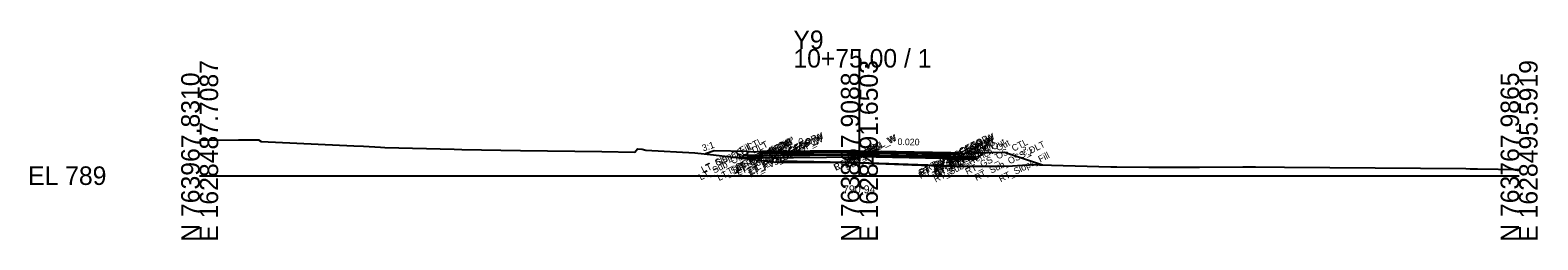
# Model space of a CAD drawing. Extents: x -26 to 203, y -10 to 6017.
# Drawn here: x -25.7 to 202.8, y 1490.3 to 1522 of the extents above; entities that cross this region are included whole.
import ezdxf

# ---------------------------------------------------------------- set-up
doc = ezdxf.new("R2010")
doc.units = 0
for name, color, linetype in [('Default', 7, 'Continuous'), ('Exist Cross Section Cell', 7, 'Continuous'), ('Exist XS Center Line Elevation Label', 7, 'Continuous'), ('Exist XS Ground Line', 7, 'Continuous'), ('Prop CMT Concrete Structures', 7, 'Continuous'), ('Prop CMT Pvmt Course 1', 7, 'Continuous'), ('Prop CMT Pvmt Course 1 Wedge', 7, 'Continuous'), ('Prop CMT Pvmt Course 2', 7, 'Continuous'), ('Prop CMT Pvmt Course 2 Wedge', 7, 'Continuous'), ('Prop CMT Pvmt Course 3', 7, 'Continuous'), ('Prop CMT Pvmt Course 3 Wedge', 7, 'Continuous'), ('Prop CMT Pvmt Surface', 7, 'Continuous'), ('Prop CMT Pvmt Surface Shoulder', 7, 'Continuous'), ('Prop CMT Pvmt Wedge Surface 2', 7, 'Continuous'), ('Prop CMT Pvmt Wedge Surface 3', 7, 'Continuous'), ('Prop CMT Shld Paved Course 1', 7, 'Continuous'), ('Prop CMT Shld Paved Course 2', 7, 'Continuous'), ('Prop CMT Shld Paved Course 3', 7, 'Continuous'), ('Prop CMT Slope Grass', 7, 'Continuous'), ('Prop CMT Subgrade Earthwork', 7, 'Continuous'), ('Prop XS SE Text', 7, 'Continuous'), ('Prop XS Side Slope Text', 7, 'Continuous'), ('Scratch_Level_0', 7, 'Continuous')]:
    doc.layers.add(name, color=color, linetype=linetype)

msp = doc.modelspace()

# ---------------------------------------------------------------- linework, layer by layer
at = {"layer": 'Exist Cross Section Cell'}
for p, q in [((100, 1500), (100, 1519.15)), ((0, 1500), (100, 1500)), ((100, 1500), (200, 1500))]:
    msp.add_line(p, q, dxfattribs=at)
at = {"layer": 'Exist XS Ground Line'}
msp.add_lwpolyline([(0, 1505.38), (5.87, 1505.43), (8.9, 1505.42), (9.31, 1505.16), (23.36, 1504.5), (24.83, 1504.44), (27.39, 1504.3), (28.08, 1504.26), (38.56, 1504.03), (39.75, 1503.98), (48.62, 1503.82), (60.96, 1503.65), (65.95, 1503.55), (66.37, 1504.05), (67.07, 1503.99), (67.63, 1503.87), (75.08, 1503.47), (77.9, 1503.15), (84.7, 1502.36), (86.09, 1502.21), (87.51, 1502.03), (94.47, 1502.03), (98.1, 1502.01), (100, 1501.94), (107.93, 1501.64), (113.86, 1501.45), (120.43, 1501.43), (120.98, 1501.45), (123.23, 1501.51), (124.73, 1501.61), (126.7, 1501.67), (127.29, 1501.65), (138.13, 1501.33), (139.04, 1501.36), (143.85, 1501.31), (148.08, 1501.31), (151.55, 1501.29), (158.1, 1501.35), (160.05, 1501.34), (164.43, 1501.31), (191.91, 1501.07), (192.59, 1501.05), (192.97, 1501.05), (193.67, 1501.04), (200, 1500.93)], dxfattribs=at)
at = {"layer": 'Prop CMT Concrete Structures'}
for points in [[(83, 1503.64), (83, 1503.06), (85, 1503.06)], [(85, 1503.64), (84, 1503.56), (83, 1503.64)], [(85, 1503.06), (85, 1503.64)], [(117, 1503.45), (117, 1502.87), (115, 1502.87)], [(115, 1503.45), (116, 1503.37), (117, 1503.45)], [(115, 1502.87), (115, 1503.45)]]:
    msp.add_lwpolyline(points, dxfattribs=at)
at = {"layer": 'Prop CMT Pvmt Course 1'}
for points in [[(100, 1503.75), (85, 1503.64)], [(100, 1503.75), (88.09, 1503.66)], [(100, 1503.63), (100, 1503.75)], [(100, 1503.5), (100, 1503.75)], [(100, 1503.75), (113.86, 1503.48)], [(100, 1503.63), (100, 1503.75)], [(100, 1503.75), (115, 1503.45)], [(100, 1503.5), (100, 1503.75)], [(85, 1503.64), (85, 1503.39)], [(85, 1503.39), (100, 1503.5)], [(115, 1503.2), (100, 1503.5)], [(115, 1503.45), (115, 1503.2)]]:
    msp.add_lwpolyline(points, dxfattribs=at)
at = {"layer": 'Prop CMT Pvmt Course 1 Wedge'}
for points in [[(100, 1503.5), (98.1, 1503.49), (88.09, 1503.41)], [(100, 1503.63), (100, 1503.5)], [(100, 1503.5), (100, 1503.63)], [(113.86, 1503.23), (111.82, 1503.27), (100, 1503.5)]]:
    msp.add_lwpolyline(points, dxfattribs=at)
at = {"layer": 'Prop CMT Pvmt Course 2'}
for points in [[(100, 1503.5), (85, 1503.39)], [(85, 1503.39), (85, 1503.06)], [(85, 1503.06), (100, 1503.17)], [(100, 1503.17), (100, 1503.5)], [(100, 1503.17), (100, 1503.5)], [(100, 1503.5), (115, 1503.2)], [(115, 1502.87), (100, 1503.17)], [(115, 1503.2), (115, 1502.87)]]:
    msp.add_lwpolyline(points, dxfattribs=at)
at = {"layer": 'Prop CMT Pvmt Course 2 Wedge'}
for points in [[(88.09, 1503.41), (98.1, 1503.49), (100, 1503.5)], [(100, 1503.17), (98.1, 1503.16), (88.09, 1503.08)], [(100, 1503.5), (100, 1503.17)], [(100, 1503.5), (111.82, 1503.27), (113.86, 1503.23)], [(100, 1503.17), (100, 1503.5)], [(113.86, 1502.89), (111.82, 1502.93), (100, 1503.17)]]:
    msp.add_lwpolyline(points, dxfattribs=at)
at = {"layer": 'Prop CMT Pvmt Course 3'}
msp.add_line((117, 1502.87), (117.5, 1502.87), dxfattribs=at)
for points in [[(100, 1503.17), (85, 1503.06)], [(85, 1503.06), (85, 1502.72)], [(85, 1502.72), (100, 1502.84)], [(100, 1502.84), (100, 1503.17)], [(100, 1503.17), (115, 1502.87)], [(100, 1502.84), (100, 1503.17)], [(115, 1502.54), (100, 1502.84)], [(115, 1502.87), (115, 1502.54)]]:
    msp.add_lwpolyline(points, dxfattribs=at)
at = {"layer": 'Prop CMT Pvmt Course 3 Wedge'}
for points in [[(88.09, 1503.08), (98.1, 1503.16), (100, 1503.17)], [(100, 1501.94), (98.1, 1502.01), (88.09, 1502.17)], [(100, 1503.17), (111.82, 1502.93), (113.86, 1502.89)], [(113.86, 1501.45), (111.82, 1501.52), (100, 1501.94)]]:
    msp.add_lwpolyline(points, dxfattribs=at)
at = {"layer": 'Prop CMT Pvmt Surface'}
for points in [[(100, 1503.75), (85, 1503.64)], [(100, 1503.75), (88.09, 1503.66)], [(100, 1503.75), (115, 1503.45)], [(100, 1503.75), (113.86, 1503.48)]]:
    msp.add_lwpolyline(points, dxfattribs=at)
at = {"layer": 'Prop CMT Pvmt Surface Shoulder'}
for points in [[(85, 1503.64), (85, 1503.64)], [(115, 1503.45), (115, 1503.45)]]:
    msp.add_lwpolyline(points, dxfattribs=at)
at = {"layer": 'Prop CMT Pvmt Wedge Surface 2'}
for points in [[(100, 1503.5), (100, 1503.75)], [(100, 1503.5), (100, 1503.75)], [(100, 1503.5), (100, 1503.75)], [(100, 1503.5), (100, 1503.75)], [(100, 1503.5), (88.09, 1503.41)], [(100, 1503.5), (113.86, 1503.23)]]:
    msp.add_lwpolyline(points, dxfattribs=at)
at = {"layer": 'Prop CMT Pvmt Wedge Surface 3'}
for points in [[(100, 1503.17), (100, 1503.75)], [(100, 1503.17), (100, 1503.75)], [(100, 1503.17), (100, 1503.75)], [(100, 1503.17), (100, 1503.75)], [(100, 1503.17), (88.09, 1503.08)], [(100, 1503.17), (113.86, 1502.89)]]:
    msp.add_lwpolyline(points, dxfattribs=at)
at = {"layer": 'Prop CMT Shld Paved Course 1'}
for points in [[(85, 1503.64), (85, 1503.64)], [(85, 1503.39), (85, 1503.64)], [(115, 1503.45), (115, 1503.45)], [(115, 1503.2), (115, 1503.45)]]:
    msp.add_lwpolyline(points, dxfattribs=at)
at = {"layer": 'Prop CMT Shld Paved Course 2'}
for p, q in [((83, 1503.06), (85, 1503.06)), ((117, 1502.87), (115, 1502.87))]:
    msp.add_line(p, q, dxfattribs=at)
for points in [[(85, 1503.06), (85, 1503.39)], [(115, 1502.87), (115, 1503.2)]]:
    msp.add_lwpolyline(points, dxfattribs=at)
at = {"layer": 'Prop CMT Shld Paved Course 3'}
for p, q in [((82.16, 1502.72), (85, 1502.72)), ((117.84, 1502.53), (115, 1502.54))]:
    msp.add_line(p, q, dxfattribs=at)
for points in [[(85, 1503.06), (83, 1503.06), (82.5, 1503.06), (82.16, 1502.72)], [(85, 1502.72), (85, 1503.06)], [(115, 1502.54), (115, 1502.87)], [(115, 1502.87), (117.5, 1502.87), (117.5, 1502.87), (117.84, 1502.53)]]:
    msp.add_lwpolyline(points, dxfattribs=at)
at = {"layer": 'Prop CMT Slope Grass'}
for points in [[(83, 1503.64), (78, 1503.74), (76.65, 1503.29)], [(117, 1503.45), (122, 1503.55), (127.75, 1501.64)]]:
    msp.add_lwpolyline(points, dxfattribs=at)
at = {"layer": 'Prop CMT Subgrade Earthwork'}
for p, q in [((82.16, 1502.72), (81.2, 1503.68)), ((85, 1502.72), (82.16, 1502.72)), ((88.09, 1502.17), (88.09, 1502.75)), ((113.86, 1501.45), (113.86, 1502.56)), ((115, 1502.54), (117.84, 1502.53)), ((117.84, 1502.53), (118.8, 1503.49))]:
    msp.add_line(p, q, dxfattribs=at)
for points in [[(88.09, 1502.75), (85, 1502.72)], [(113.86, 1502.56), (115, 1502.54)]]:
    msp.add_lwpolyline(points, dxfattribs=at)

# ---------------------------------------------------------------- texts
at = {"layer": 'Default'}
msp.add_text('-', height=0.0001, dxfattribs=at).set_placement((0, 1500))
at = {"layer": 'Exist Cross Section Cell'}
for s, p in [('Y9', (90, 1519.15)), ('10+75.00 / 1', (90, 1516.35)), ('EL 789', (-26, 1498.6))]:
    msp.add_text(s, height=2.8, dxfattribs=at).set_placement(p)
for s, p in [('N 763967.8310', (0, 1490)), ('E 1628487.7087', (2.8, 1490)), ('N 763867.9088', (100, 1490)), ('E 1628491.6503', (102.8, 1490)), ('N 763767.9865', (200, 1490)), ('E 1628495.5919', (202.8, 1490))]:
    msp.add_text(s, height=2.8, rotation=90, dxfattribs=at).set_placement(p)
at = {"layer": 'Exist XS Center Line Elevation Label'}
msp.add_text('790.94', height=1.2, dxfattribs=at).set_placement((97.52, 1497.34))
at = {"layer": 'Prop XS SE Text'}
for s, rotation, p in [('0.007', 0.4297, (90.74, 1504.68)), ('0.020', 358.8542, (105.77, 1504.64))]:
    msp.add_text(s, height=1, rotation=rotation, dxfattribs=at).set_placement(p)
at = {"layer": 'Prop XS Side Slope Text'}
for rotation, p in [(18.4349, (76.35, 1503.66)), (341.5651, (124.4, 1503.52))]:
    msp.add_text('3:1', height=1, rotation=rotation, dxfattribs=at).set_placement(p)
at = {"layer": 'Scratch_Level_0'}
for s, p in [('LT_PV2_OEEOP_W', (83.56, 1500.03)), ('LT_PV3_OEEOP_W', (83.56, 1499.7)), ('LT_PV1_OEEOP_W', (83.66, 1500.21)), ('LT_PV1_OEEOP', (84.52, 1500.76)), ('RT_PV1_PGL_W', (96.41, 1500.72)), ('LT_PV1_PGL_W', (96.47, 1500.74)), ('RT_PV2_OEEOP_W', (109.28, 1499.82)), ('RT_PV1_OEEOP_W', (109.38, 1499.99)), ('RT_PV1_OEEOP', (110.24, 1500.55)), ('LT_Sub_OSS_DLT', (75.95, 1499.28)), ('LT_Slope_Fill', (76.33, 1500.41)), ('LT_GS_OS_CTL', (76.39, 1500.32)), ('LT_Sub_Trench_Out', (78.74, 1499.17)), ('LT_PS3_Shelf_Out', (79.57, 1499.75)), ('LT_PS3_OEOP', (81.08, 1500.27)), ('LT_PS2_OEOP', (81.42, 1500.61)), ('LT_PV2_OEOT', (81.64, 1500.59)), ('LT_PV3_OEOT', (81.64, 1500.26)), ('LT_Sub_OEOT', (81.66, 1499.94)), ('LT_PV1_OEOT', (81.75, 1500.9)), ('LT_PS1_OEOP', (81.79, 1500.92)), ('PV2_PGL', (98.08, 1501.42)), ('PV3_PGL', (98.08, 1501.09)), ('Sub_PGL', (98.1, 1500.77)), ('PV1_PGL', (98.18, 1501.73)), ('RT_PV3_OEEOP_W', (109.28, 1499.48)), ('RT_Sub_Trench_Out', (111.56, 1498.95)), ('RT_PV2_OEOT', (111.59, 1500.38)), ('RT_PV3_OEOT', (111.59, 1500.05)), ('RT_Sub_OEOT', (111.61, 1499.72)), ('RT_PV1_OEOT', (111.7, 1500.68)), ('RT_PS3_Shelf_Out', (111.71, 1499.54)), ('RT_PS1_OEOP', (111.73, 1500.7)), ('RT_PS2_OEOP', (111.88, 1500.39)), ('RT_PS3_OEOP', (112.22, 1500.05)), ('RT_GS_OS_CTL', (116.34, 1500.1)), ('RT_Sub_OSS_DLT', (117.75, 1499.17)), ('RT_Slope_Fill', (121.42, 1498.99))]:
    msp.add_text(s, height=1, rotation=26.5651, dxfattribs=at).set_placement(p)

doc.saveas('drawing.dxf')
